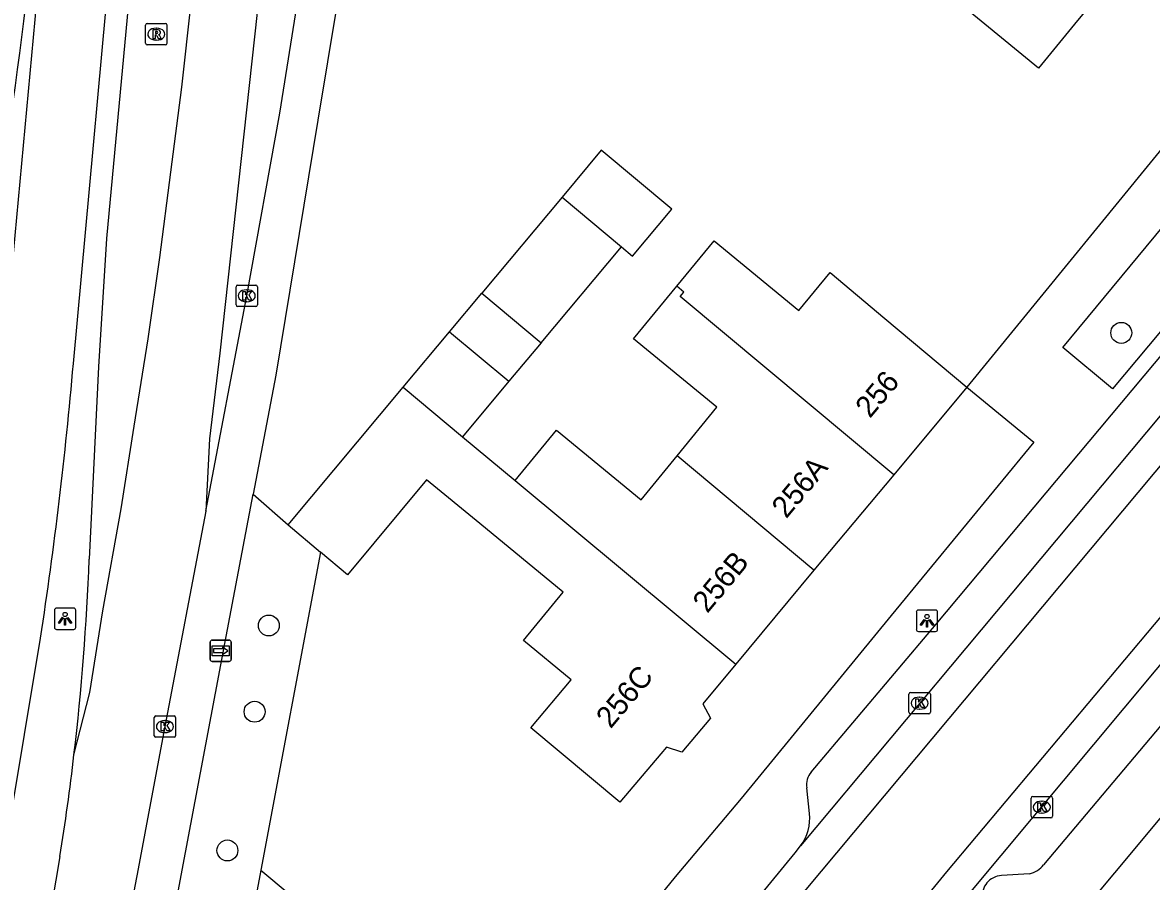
# Model space of a CAD drawing. Extents: x 160158 to 160921, y 381517 to 382041.
# Drawn here: x 160525.6 to 160578.4, y 381762.5 to 381802.7 of the extents above; entities that cross this region are included whole.
import ezdxf

# ---------------------------------------------------------------- set-up
doc = ezdxf.new("R2010")
doc.units = 0
for name, color, linetype in [('IMGEO_Berm_groen', 7, 'Continuous'), ('IMGEO_Boom', 7, 'Continuous'), ('IMGEO_Groenvoorziening', 7, 'Continuous'), ('IMGEO_Kolk', 7, 'Continuous'), ('IMGEO_Lichtpunt', 7, 'Continuous'), ('IMGEO_Muur', 7, 'Continuous'), ('IMGEO_Pand', 7, 'Continuous'), ('IMGEO_Pand_nummerreeks', 7, 'Continuous'), ('IMGEO_Rijbaan_lokaal_gesloten', 7, 'Continuous'), ('IMGEO_Rijbaan_regionaal_gesloten', 7, 'Continuous'), ('IMGEO_Rioolput', 7, 'Continuous'), ('IMGEO_Voetpad_open', 7, 'Continuous'), ('IMGEO_Wegwijzer', 7, 'Continuous')]:
    doc.layers.add(name, color=color, linetype=linetype)

msp = doc.modelspace()

# ---------------------------------------------------------------- linework, layer by layer
at = {"layer": 'IMGEO_Berm_groen'}
for centre, radius, start, end in [((160083.837, 381858.802), 442.519, 350.5442, 356.78225), ((160153.748, 381850.796), 375.027, 349.97715, 357.39851)]:
    msp.add_arc(centre, radius, start, end, dxfattribs=at)
at = {"layer": 'IMGEO_Boom'}
for centre in [(160577.013, 381788.2), (160537.142, 381774.514), (160536.478, 381770.482), (160535.206, 381763.995)]:
    msp.add_circle(centre, 0.489, dxfattribs=at)
at = {"layer": 'IMGEO_Groenvoorziening'}
for points in [[(160536.414, 381780.659), (160538.044, 381779.218)], [(160539.559, 381777.945), (160536.769, 381763.076)]]:
    msp.add_lwpolyline(points, dxfattribs=at)
at = {"layer": 'IMGEO_Kolk'}
for p, q in [((160535.683, 381790.435), (160536.535, 381790.435)), ((160535.608, 381789.509), (160535.608, 381790.361)), ((160536.096, 381790.215), (160536.121, 381790.215)), ((160536.609, 381790.361), (160536.609, 381789.509)), ((160536.535, 381789.435), (160535.683, 381789.435)), ((160536.119, 381789.655), (160536.094, 381789.655)), ((160567.083, 381770.456), (160567.083, 381771.308)), ((160567.158, 381771.382), (160568.01, 381771.382)), ((160567.571, 381771.162), (160567.596, 381771.162)), ((160568.084, 381771.308), (160568.084, 381770.456)), ((160568.01, 381770.382), (160567.158, 381770.382)), ((160567.594, 381770.602), (160567.569, 381770.602)), ((160531.782, 381769.361), (160531.782, 381770.213)), ((160531.857, 381770.287), (160532.709, 381770.287)), ((160532.27, 381770.067), (160532.295, 381770.067)), ((160532.783, 381770.213), (160532.783, 381769.361)), ((160532.293, 381769.507), (160532.268, 381769.507)), ((160532.709, 381769.287), (160531.857, 381769.287)), ((160572.794, 381765.595), (160572.794, 381766.447)), ((160572.869, 381766.521), (160573.721, 381766.521)), ((160573.282, 381766.301), (160573.307, 381766.301)), ((160573.795, 381766.447), (160573.795, 381765.595)), ((160573.305, 381765.741), (160573.28, 381765.741)), ((160573.721, 381765.521), (160572.869, 381765.521))]:
    msp.add_line(p, q, dxfattribs=at)
for points in [[(160535.683, 381790.435), (160536.535, 381790.435)], [(160535.608, 381789.509), (160535.608, 381790.361)], [(160535.929, 381790.135), (160536.052, 381790.135), (160536.052, 381789.984), (160536.182, 381790.135), (160536.346, 381790.135), (160536.2, 381789.984), (160536.353, 381789.735), (160536.201, 381789.735), (160536.116, 381789.899), (160536.052, 381789.832), (160536.052, 381789.735), (160535.929, 381789.735), (160535.929, 381790.135)], [(160536.609, 381790.361), (160536.609, 381789.509)], [(160536.535, 381789.435), (160535.683, 381789.435)], [(160567.083, 381770.456), (160567.083, 381771.308)], [(160567.158, 381771.382), (160568.01, 381771.382)], [(160567.404, 381771.082), (160567.527, 381771.082), (160567.527, 381770.931), (160567.657, 381771.082), (160567.821, 381771.082), (160567.675, 381770.931), (160567.828, 381770.682), (160567.676, 381770.682), (160567.591, 381770.846), (160567.527, 381770.779), (160567.527, 381770.682), (160567.404, 381770.682), (160567.404, 381771.082)], [(160568.084, 381771.308), (160568.084, 381770.456)], [(160568.01, 381770.382), (160567.158, 381770.382)], [(160531.782, 381769.361), (160531.782, 381770.213)], [(160531.857, 381770.287), (160532.709, 381770.287)], [(160532.103, 381769.987), (160532.226, 381769.987), (160532.226, 381769.836), (160532.356, 381769.987), (160532.52, 381769.987), (160532.374, 381769.836), (160532.527, 381769.587), (160532.375, 381769.587), (160532.29, 381769.751), (160532.226, 381769.684), (160532.226, 381769.587), (160532.103, 381769.587), (160532.103, 381769.987)], [(160532.783, 381770.213), (160532.783, 381769.361)], [(160532.709, 381769.287), (160531.857, 381769.287)], [(160572.794, 381765.595), (160572.794, 381766.447)], [(160572.869, 381766.521), (160573.721, 381766.521)], [(160573.115, 381766.221), (160573.238, 381766.221), (160573.238, 381766.07), (160573.368, 381766.221), (160573.532, 381766.221), (160573.386, 381766.07), (160573.539, 381765.821), (160573.387, 381765.821), (160573.302, 381765.985), (160573.238, 381765.918), (160573.238, 381765.821), (160573.115, 381765.821), (160573.115, 381766.221)], [(160573.795, 381766.447), (160573.795, 381765.595)], [(160573.721, 381765.521), (160572.869, 381765.521)]]:
    msp.add_lwpolyline(points, dxfattribs=at)
for centre, start, end in [((160535.685, 381790.359), 91.552, 178.448), ((160535.685, 381790.359), 91.552, 178.448), ((160536.533, 381790.359), 1.552, 88.448), ((160536.533, 381790.359), 1.552, 88.448), ((160535.685, 381789.511), 181.552, 268.448), ((160535.685, 381789.511), 181.552, 268.448), ((160536.533, 381789.511), 271.552, 358.448), ((160536.533, 381789.511), 271.552, 358.448), ((160567.16, 381771.306), 91.552, 178.448), ((160567.16, 381771.306), 91.552, 178.448), ((160568.008, 381771.306), 1.552, 88.448), ((160568.008, 381771.306), 1.552, 88.448), ((160567.16, 381770.458), 181.552, 268.448), ((160567.16, 381770.458), 181.552, 268.448), ((160568.008, 381770.458), 271.552, 358.448), ((160568.008, 381770.458), 271.552, 358.448), ((160531.859, 381770.211), 91.552, 178.448), ((160531.859, 381770.211), 91.552, 178.448), ((160532.707, 381770.211), 1.552, 88.448), ((160532.707, 381770.211), 1.552, 88.448), ((160531.859, 381769.363), 181.552, 268.448), ((160531.859, 381769.363), 181.552, 268.448), ((160532.707, 381769.363), 271.552, 358.448), ((160532.707, 381769.363), 271.552, 358.448), ((160572.871, 381766.445), 91.552, 178.448), ((160572.871, 381766.445), 91.552, 178.448), ((160573.719, 381766.445), 1.552, 88.448), ((160573.719, 381766.445), 1.552, 88.448), ((160572.871, 381765.597), 181.552, 268.448), ((160572.871, 381765.597), 181.552, 268.448), ((160573.719, 381765.597), 271.552, 358.448), ((160573.719, 381765.597), 271.552, 358.448)]:
    msp.add_arc(centre, 0.0765, start, end, dxfattribs=at)
for centre, major_axis, ratio, start_param, end_param in [((160536.095, 381789.935), (-0.387, 0.002), 0.722429, 4.712389, 7.853982), ((160536.12, 381789.935), (-0.39, 0.002), 0.717154, 1.570796, 4.712389), ((160567.57, 381770.882), (-0.387, 0.002), 0.722429, 4.712389, 7.853982), ((160567.595, 381770.882), (-0.39, 0.002), 0.717154, 1.570796, 4.712389), ((160532.269, 381769.787), (-0.387, 0.002), 0.722429, 4.712389, 7.853982), ((160532.294, 381769.787), (-0.39, 0.002), 0.717154, 1.570796, 4.712389), ((160573.281, 381766.021), (-0.387, 0.002), 0.722429, 4.712389, 7.853982), ((160573.306, 381766.021), (-0.39, 0.002), 0.717154, 1.570796, 4.712389)]:
    msp.add_ellipse(centre, major_axis=major_axis, ratio=ratio, start_param=start_param, end_param=end_param, dxfattribs=at)
at = {"layer": 'IMGEO_Lichtpunt'}
for p, q in [((160527.117, 381775.233), (160527.117, 381774.426)), ((160527.117, 381775.233), (160527.117, 381774.426)), ((160528.019, 381775.328), (160527.211, 381775.328)), ((160528.019, 381775.328), (160527.211, 381775.328)), ((160528.113, 381774.426), (160528.113, 381775.233)), ((160528.113, 381774.426), (160528.113, 381775.233)), ((160567.427, 381775.139), (160567.427, 381774.332)), ((160567.427, 381775.139), (160567.427, 381774.332)), ((160568.329, 381775.234), (160567.521, 381775.234)), ((160568.329, 381775.234), (160567.521, 381775.234)), ((160568.423, 381774.332), (160568.423, 381775.139)), ((160568.423, 381774.332), (160568.423, 381775.139)), ((160527.211, 381774.332), (160528.019, 381774.332)), ((160527.211, 381774.332), (160528.019, 381774.332)), ((160567.521, 381774.238), (160568.329, 381774.238)), ((160567.521, 381774.238), (160568.329, 381774.238))]:
    msp.add_line(p, q, dxfattribs=at)
for points in [[(160527.491, 381774.897), (160527.53, 381774.869), (160527.342, 381774.607), (160527.304, 381774.634), (160527.491, 381774.897)], [(160527.593, 381774.849), (160527.64, 381774.849), (160527.64, 381774.527), (160527.593, 381774.527), (160527.593, 381774.849)], [(160527.703, 381774.869), (160527.741, 381774.896), (160527.928, 381774.634), (160527.889, 381774.606), (160527.703, 381774.869)], [(160567.801, 381774.803), (160567.84, 381774.775), (160567.652, 381774.513), (160567.614, 381774.54), (160567.801, 381774.803)], [(160567.903, 381774.755), (160567.95, 381774.755), (160567.95, 381774.433), (160567.903, 381774.433), (160567.903, 381774.755)], [(160568.013, 381774.775), (160568.051, 381774.802), (160568.238, 381774.54), (160568.199, 381774.512), (160568.013, 381774.775)]]:
    msp.add_lwpolyline(points, dxfattribs=at)
for centre in [(160527.616, 381775.031), (160567.926, 381774.937)]:
    msp.add_circle(centre, 0.0994, dxfattribs=at)
for centre, start, end in [((160527.211, 381775.233), 90, 180), ((160527.211, 381775.233), 90, 180), ((160528.019, 381775.233), 0, 90), ((160528.019, 381775.233), 0, 90), ((160567.521, 381775.139), 90, 180), ((160567.521, 381775.139), 90, 180), ((160568.329, 381775.139), 0, 90), ((160568.329, 381775.139), 0, 90), ((160527.211, 381774.426), 180, 270), ((160527.211, 381774.426), 180, 270), ((160528.019, 381774.426), 270, 0), ((160528.019, 381774.426), 270, 360), ((160567.521, 381774.332), 180, 270), ((160567.521, 381774.332), 180, 270), ((160568.329, 381774.332), 270, 0), ((160568.329, 381774.332), 270, 360)]:
    msp.add_arc(centre, 0.0946, start, end, dxfattribs=at)
at = {"layer": 'IMGEO_Muur'}
msp.add_lwpolyline([(160539.559, 381777.945), (160536.769, 381763.076)], dxfattribs=at)
at = {"layer": 'IMGEO_Pand'}
for points in [[(160587.941, 381807.827), (160578.412, 381815.643), (160573.653, 381809.843), (160577.89, 381806.362), (160574.832, 381802.642), (160573.135, 381800.579), (160565.264, 381807.052), (160552.423, 381807.918), (160552.339, 381806.92), (160545.043, 381807.398), (160545.119, 381808.768), (160544.205, 381808.84)], [(160553.637, 381792.229), (160554.156, 381791.795), (160555.991, 381793.99), (160552.693, 381796.747), (160550.859, 381794.551)], [(160550.859, 381794.551), (160547.107, 381790.062)], [(160550.859, 381794.551), (160553.637, 381792.229)], [(160549.884, 381787.74), (160553.637, 381792.229)], [(160556.228, 381790.387), (160557.966, 381792.501), (160561.933, 381789.24), (160563.395, 381791.018), (160565.952, 381788.876), (160569.786, 381785.666)], [(160545.598, 381788.256), (160547.107, 381790.062)], [(160547.107, 381790.062), (160549.884, 381787.74)], [(160556.234, 381782.446), (160558.103, 381784.719), (160554.204, 381787.925), (160556.228, 381790.387)], [(160566.367, 381781.567), (160556.386, 381789.906), (160556.558, 381790.111), (160556.228, 381790.387)], [(160543.426, 381785.657), (160545.598, 381788.256)], [(160545.598, 381788.256), (160548.375, 381785.935)], [(160549.884, 381787.74), (160548.375, 381785.935)], [(160548.375, 381785.935), (160546.207, 381783.342)], [(160538.044, 381779.218), (160543.426, 381785.657)], [(160543.426, 381785.657), (160546.207, 381783.342)], [(160569.786, 381785.666), (160566.367, 381781.567)], [(160548.665, 381781.296), (160550.599, 381783.648), (160554.551, 381780.398), (160556.234, 381782.446)], [(160546.207, 381783.342), (160548.665, 381781.296)], [(160562.638, 381777.096), (160556.234, 381782.446)], [(160566.367, 381781.567), (160562.638, 381777.096)], [(160558.979, 381772.71), (160557.434, 381770.858), (160557.796, 381770.185), (160556.453, 381768.597), (160555.742, 381768.829), (160555.484, 381768.52), (160553.562, 381766.248), (160549.402, 381769.734), (160551.278, 381771.979), (160549.047, 381773.813), (160550.909, 381776.077), (160547.01, 381779.283), (160544.524, 381781.328), (160540.815, 381776.891), (160539.559, 381777.945)], [(160548.665, 381781.296), (160558.979, 381772.71)], [(160538.044, 381779.218), (160539.559, 381777.945)], [(160562.638, 381777.096), (160558.979, 381772.71)], [(160536.769, 381763.076), (160535.455, 381756.063), (160534.647, 381751.702), (160537.22, 381749.558), (160541.708, 381745.82), (160546.621, 381751.714)], [(160536.769, 381763.076), (160539.423, 381760.856), (160543.658, 381757.346), (160545.757, 381755.618), (160544.18, 381753.74), (160546.621, 381751.714)]]:
    msp.add_lwpolyline(points, dxfattribs=at)
at = {"layer": 'IMGEO_Rijbaan_lokaal_gesloten'}
for points in [[(160556.164, 381754.68), (160558.112, 381757.129), (160560.755, 381760.365), (160581.539, 381785.212), (160597.19, 381803.934)], [(160600.729, 381800.991), (160582.713, 381779.526), (160568.843, 381763.002), (160559.601, 381751.709)], [(160559.501, 381749.238), (160560.113, 381750), (160567.175, 381758.693), (160571.401, 381763.753), (160601.731, 381800.097)], [(160588.465, 381796.32), (160588.699, 381796.124), (160587.352, 381794.513), (160562.011, 381764.214)], [(160556.569, 381757.556), (160561.758, 381763.877), (160562.011, 381764.214)]]:
    msp.add_lwpolyline(points, dxfattribs=at)
at = {"layer": 'IMGEO_Rijbaan_regionaal_gesloten'}
for points in [[(160550.864, 381933.395), (160546.378, 381915.31), (160545.363, 381910.49), (160544.695, 381906.619), (160543.942, 381898.777), (160543.305, 381890.839), (160542.819, 381882.725), (160542.25, 381874.861), (160541.681, 381866.997), (160541.102, 381859.002), (160540.524, 381851.007), (160539.955, 381843.146), (160539.359, 381834.905), (160538.673, 381827.033), (160537.978, 381819.053), (160537.291, 381811.172), (160536.596, 381803.188), (160535.72, 381795.222), (160534.845, 381787.255), (160534.361, 381783.239), (160534.195, 381779.861)], [(160534.257, 381910.641), (160533, 381891.221), (160531.52, 381869.788), (160530.173, 381850.327), (160528.774, 381830.898), (160527.114, 381812.495), (160526.59, 381807.082), (160525.11, 381791.078), (160524.523, 381784.877), (160523.992, 381779.798)], [(160528.001, 381786.763), (160532.157, 381832.058), (160533.178, 381846.489), (160535.336, 381877.881), (160537.367, 381907.526)], [(160538.181, 381902.406), (160536.45, 381877.717), (160534.083, 381843.54), (160533.226, 381832.551), (160532.528, 381824.512), (160529.545, 381792.616), (160529.18, 381786.609), (160528.742, 381777.62)], [(160528.03, 381768.466), (160528.772, 381771.385), (160529.38, 381775.201), (160530.233, 381779.971), (160530.846, 381783.843), (160531.492, 381787.917), (160532.039, 381791.732), (160532.56, 381795.716), (160533.081, 381799.699), (160533.505, 381803.628), (160533.879, 381807.453), (160534.286, 381811.605), (160534.615, 381815.481), (160534.979, 381819.427), (160535.347, 381823.421), (160535.652, 381827.333), (160536.375, 381835.269), (160536.668, 381839.437), (160536.997, 381843.386), (160537.55, 381851.139)], [(160534.195, 381779.861), (160536.108, 381789.935), (160537.65, 381798.47), (160538.964, 381806.709), (160539.588, 381811.172), (160540.822, 381821.339)], [(160534.195, 381779.861), (160532.282, 381769.787), (160531.658, 381766.473), (160531.031, 381763.137), (160529.214, 381753.603), (160528.561, 381750), (160528.299, 381748.554)], [(160521.362, 381746.238), (160522.088, 381750), (160524.967, 381764.913), (160526.466, 381773.924)], [(160527.375, 381763.707), (160525.853, 381754.764), (160525.07, 381750), (160524.88, 381748.845)]]:
    msp.add_lwpolyline(points, dxfattribs=at)
for centre, radius, start, end in [((160328.232, 381804.136), 200.523, 351.33458, 355.02985), ((160410.748, 381782.193), 118.083, 353.32437, 357.78058), ((160412.245, 381781.977), 116.571, 350.98273, 353.34405)]:
    msp.add_arc(centre, radius, start, end, dxfattribs=at)
at = {"layer": 'IMGEO_Rioolput'}
for p, q in [((160531.379, 381801.744), (160531.379, 381802.596)), ((160531.454, 381802.67), (160532.306, 381802.67)), ((160532.38, 381802.596), (160532.38, 381801.744)), ((160531.867, 381802.45), (160531.892, 381802.45)), ((160532.306, 381801.67), (160531.454, 381801.67)), ((160531.89, 381801.89), (160531.865, 381801.89))]:
    msp.add_line(p, q, dxfattribs=at)
for points in [[(160531.379, 381801.744), (160531.379, 381802.596)], [(160531.454, 381802.67), (160532.306, 381802.67)], [(160532.38, 381802.596), (160532.38, 381801.744)], [(160531.968, 381802.368), (160531.716, 381802.37), (160531.716, 381801.97)], [(160531.716, 381801.97), (160531.84, 381801.97), (160531.84, 381802.132), (160531.851, 381802.132)], [(160531.894, 381802.289), (160531.84, 381802.289), (160531.84, 381802.208)], [(160531.84, 381802.208), (160531.892, 381802.208)], [(160531.898, 381802.103), (160531.969, 381801.97), (160532.109, 381801.97), (160532.044, 381802.096)], [(160532.306, 381801.67), (160531.454, 381801.67)]]:
    msp.add_lwpolyline(points, dxfattribs=at)
for centre, radius, start, end in [((160531.456, 381802.594), 0.0765, 91.552, 178.448), ((160531.456, 381802.594), 0.0765, 91.552, 178.448), ((160532.304, 381802.594), 0.0765, 1.552, 88.448), ((160532.304, 381802.594), 0.0765, 1.552, 88.448), ((160531.85, 381802.079), 0.0533, 26.0293, 88.6989), ((160531.876, 381802.397), 0.19, 274.7715, 282.9687), ((160531.9, 381802.193), 0.0964, 77.0061, 93.1865), ((160531.914, 381802.25), 0.0378, 276.6634, 79.6772), ((160531.967, 381802.258), 0.109, 350.3612, 89.416), ((160531.965, 381802.258), 0.112, 277.5842, 350.9817), ((160531.949, 381802.043), 0.108, 29.5134, 73.7905), ((160531.456, 381801.746), 0.0765, 181.552, 268.448), ((160531.456, 381801.746), 0.0765, 181.552, 268.448), ((160532.304, 381801.746), 0.0765, 271.552, 358.448), ((160532.304, 381801.746), 0.0765, 271.552, 358.448)]:
    msp.add_arc(centre, radius, start, end, dxfattribs=at)
for centre, major_axis, ratio, start_param, end_param in [((160531.866, 381802.17), (-0.387, 0.002), 0.722429, 4.712389, 7.853982), ((160531.891, 381802.17), (-0.39, 0.002), 0.717154, 1.570796, 4.712389)]:
    msp.add_ellipse(centre, major_axis=major_axis, ratio=ratio, start_param=start_param, end_param=end_param, dxfattribs=at)
at = {"layer": 'IMGEO_Voetpad_open'}
for points in [[(160543.837, 381826.73), (160543.619, 381823.508), (160540.802, 381806.439), (160539.434, 381798.152), (160537.466, 381786.23), (160536.414, 381780.659)], [(160587.941, 381807.827), (160580.593, 381798.887), (160569.786, 381785.666)], [(160588.465, 381799.75), (160576.606, 381785.578), (160574.286, 381787.517), (160586.055, 381801.74), (160588.465, 381799.75)], [(160562.514, 381767.661), (160568.354, 381774.575), (160585.728, 381795.315)], [(160569.786, 381785.666), (160572.924, 381783.093), (160566.256, 381774.976), (160559.232, 381766.417), (160556.812, 381763.555), (160556.143, 381762.763), (160552.4, 381758.139), (160548.643, 381753.199), (160547.737, 381752.007), (160547.187, 381751.244)], [(160530.838, 381750), (160530.76, 381750.659), (160531.549, 381754.827), (160533.001, 381762.573), (160535.155, 381773.997), (160536.414, 381780.659)], [(160584.925, 381777.042), (160573.379, 381763.328)], [(160561.169, 381743.908), (160564.062, 381747.78), (160565.914, 381750), (160580.313, 381767.268)], [(160562.425, 381765.73), (160562.299, 381766.924)], [(160572.721, 381762.903), (160571.408, 381762.818)]]:
    msp.add_lwpolyline(points, dxfattribs=at)
for centre, radius, start, end in [((160563.168, 381767.07), 0.881, 137.9186, 189.5551), ((160560.406, 381765.467), 2.036, 322.0296, 7.4218), ((160572.48, 381763.998), 1.122, 282.4221, 323.2945), ((160571.462, 381761.864), 0.956, 93.265, 186.5962)]:
    msp.add_arc(centre, radius, start, end, dxfattribs=at)
at = {"layer": 'IMGEO_Wegwijzer'}
for p, q in [((160534.397, 381772.932), (160534.397, 381773.732)), ((160534.397, 381773.732), (160534.397, 381772.932)), ((160534.497, 381773.832), (160535.287, 381773.832)), ((160535.287, 381773.832), (160534.497, 381773.832)), ((160535.387, 381773.732), (160535.387, 381772.932)), ((160535.387, 381772.932), (160535.387, 381773.732)), ((160535.287, 381772.832), (160534.497, 381772.832)), ((160534.497, 381772.832), (160535.287, 381772.832))]:
    msp.add_line(p, q, dxfattribs=at)
for points in [[(160534.498, 381773.564), (160535.286, 381773.564), (160535.286, 381773.1), (160534.498, 381773.1), (160534.498, 381773.564)], [(160534.563, 381773.416), (160534.563, 381773.332), (160534.563, 381773.248), (160534.974, 381773.248), (160534.974, 381773.165), (160535.221, 381773.332), (160534.974, 381773.499), (160534.974, 381773.416), (160534.563, 381773.416)]]:
    msp.add_lwpolyline(points, dxfattribs=at)
for centre, start, end in [((160534.497, 381773.732), 90, 180), ((160534.497, 381773.732), 90, 180), ((160535.287, 381773.732), 0, 90), ((160535.287, 381773.732), 360, 90), ((160534.497, 381772.932), 180, 270), ((160534.497, 381772.932), 180, 270), ((160535.287, 381772.932), 270, 0), ((160535.287, 381772.932), 270, 0)]:
    msp.add_arc(centre, 0.1, start, end, dxfattribs=at)

# ---------------------------------------------------------------- texts
at = {"layer": 'IMGEO_Pand_nummerreeks'}
for s, rotation, p in [('256', 50.1675, (160565.258, 381784.172)), ('256A', 50.1675, (160561.345, 381779.481)), ('256B', 50.1675, (160557.651, 381775.053)), ('256C', 50.0274, (160553.129, 381769.655))]:
    msp.add_text(s, height=1, rotation=rotation, dxfattribs=at).set_placement(p)

doc.saveas('drawing.dxf')
